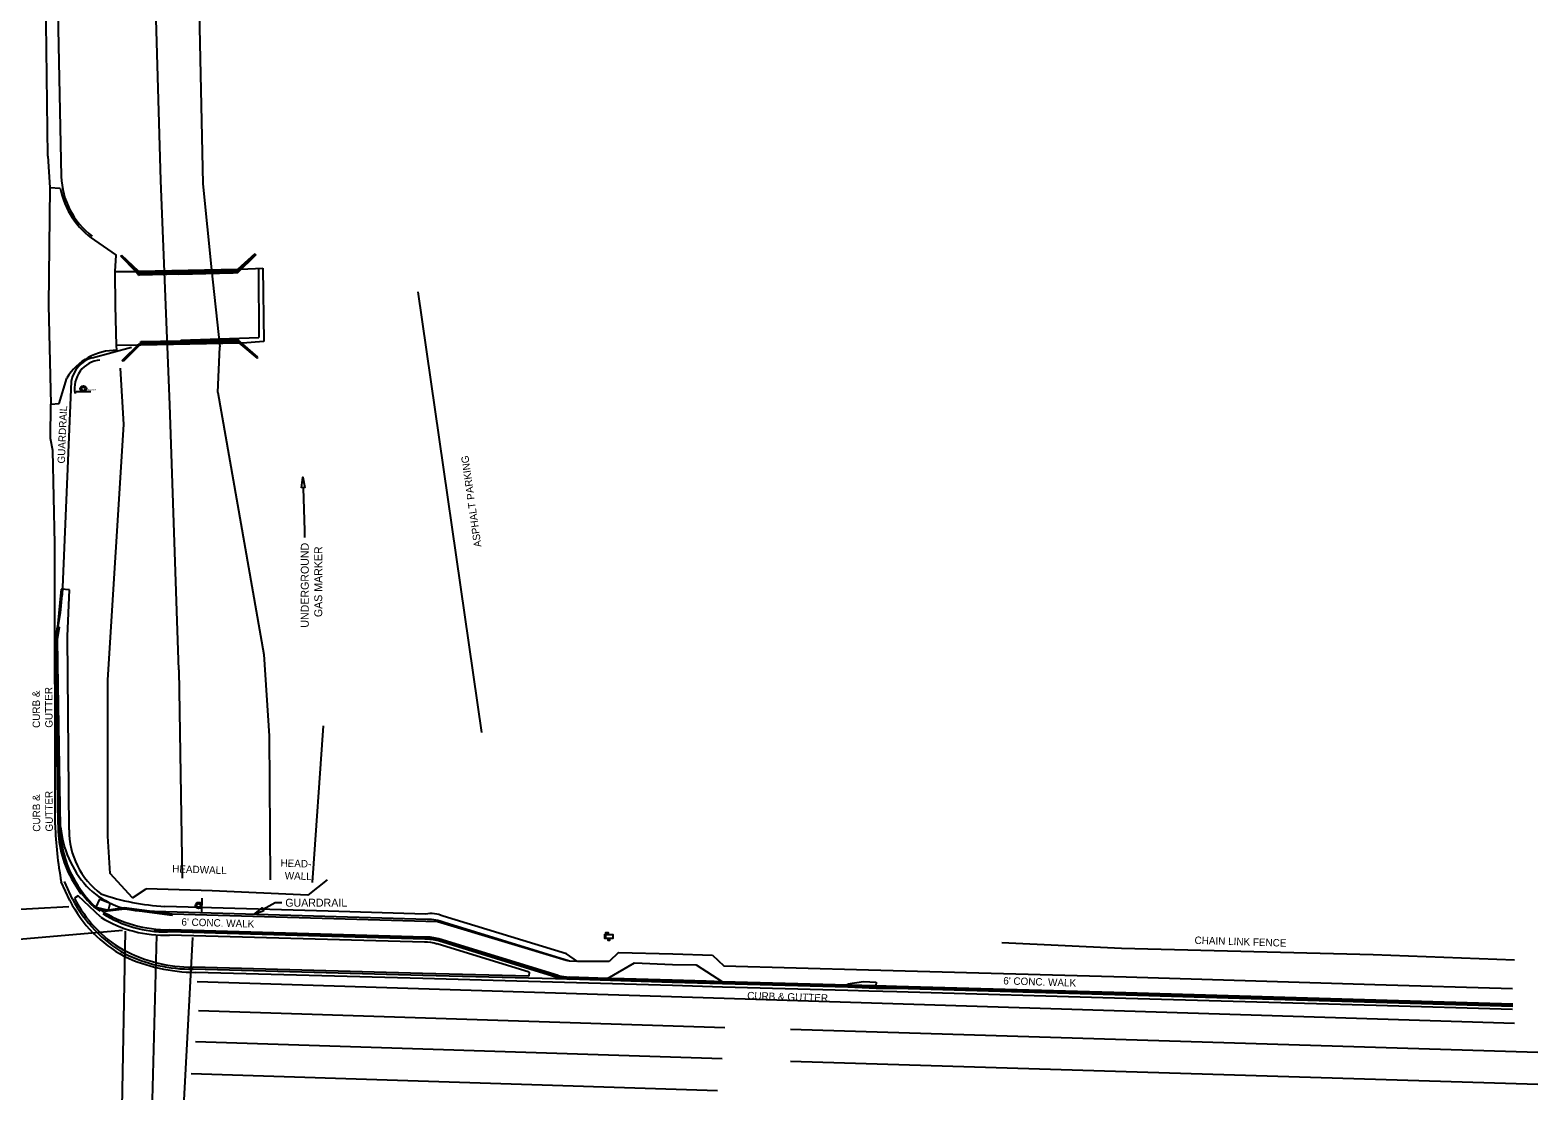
# Model space of a CAD drawing. Extents: x 925226 to 926411, y 852913 to 858733.
# Drawn here: x 925841 to 926411, y 853587 to 853988 of the extents above; entities that cross this region are included whole.
import ezdxf

# ---------------------------------------------------------------- set-up
doc = ezdxf.new("R2010")
doc.units = 0
for name, color, linetype in [('BankMent_ep', 7, 'Continuous'), ('Bridge_ep', 7, 'Continuous'), ('CGep_ep', 7, 'Continuous'), ('CGFace_ep', 7, 'Continuous'), ('CLConst_dp', 7, 'Continuous'), ('ConcSlabs_ep', 7, 'Continuous'), ('CurveData_dp', 7, 'Continuous'), ('EndTreat_ep', 7, 'Continuous'), ('Fence_ep', 7, 'Continuous'), ('Gates_ep', 7, 'Continuous'), ('GuardrailRt_ep', 7, 'Continuous'), ('InletCurb_ep', 7, 'Continuous'), ('LaneLine_ep', 7, 'Continuous'), ('ManholeSW_ep', 7, 'Continuous'), ('PavtAsphalt_ep', 7, 'Continuous'), ('PavtMisc_ep', 7, 'Continuous'), ('SidewalkBack_ep', 7, 'Continuous'), ('SidewalkFront_ep', 7, 'Continuous'), ('TextLabel', 7, 'Continuous'), ('Wall_ep', 7, 'Continuous'), ('WaterEdge_ep', 7, 'Continuous'), ('XSPt_ep', 7, 'Continuous')]:
    doc.layers.add(name, color=color, linetype=linetype)

# ---------------------------------------------------------------- blocks, each defined once
blk = doc.blocks.new('SSS')
at = {"layer": 'ManholeSW_ep'}
blk.add_line((-2.77, 1.15), (2.77, 1.15), dxfattribs=at)
for radius in [1.15, 0.692]:
    blk.add_circle((0, 0), radius, dxfattribs=at)
blk = doc.blocks.new('MBX')
at = {"layer": 'InletCurb_ep'}
for points in [[(-1.5, 1.42), (-1.5, 1.45), (1.5, 1.45), (1.5, 0), (-1.5, 0), (-1.5, 1.42), (-1.53, 1.55), (-1.59, 1.55)], [(-1.15, 0.38), (-1.15, 2.22), (-0.33, 2.22), (-0.33, 1.7), (-1.15, 1.7)], [(0.26, 0), (0.26, -0.82), (-0.26, -0.82), (-0.26, 0)]]:
    blk.add_lwpolyline(points, dxfattribs=at)

msp = doc.modelspace()

# ---------------------------------------------------------------- linework, layer by layer
at = {"layer": 'BankMent_ep'}
for p, q in [((925876.44, 853839.31), (925875.18, 853860.58)), ((925870.39, 853742.68), (925876.44, 853839.31)), ((925870.45, 853683.6), (925870.39, 853742.68)), ((925951.92, 853725.35), (925947.74, 853665.99)), ((925871.27, 853669.48), (925870.45, 853683.6)), ((925879.75, 853660.25), (925871.27, 853669.48)), ((925879.75, 853660.25), (925884.96, 853663.59)), ((925909.87, 853662.89), (925884.96, 853663.59)), ((925953.4, 853667.04), (925946.05, 853661.26)), ((925946.05, 853661.26), (925909.87, 853662.89))]:
    msp.add_line(p, q, dxfattribs=at)
at = {"layer": 'Bridge_ep'}
for p, q in [((925873.15, 853897.17), (925881.02, 853897.13)), ((925882.05, 853897.32), (925919.48, 853897.96)), ((925920.64, 853898.07), (925929.06, 853898.46)), ((925929.06, 853898.46), (925929.41, 853870.63)), ((925881.54, 853869.34), (925873.74, 853869.22)), ((925882.92, 853869.31), (925881.54, 853869.34)), ((925920.14, 853870.02), (925882.92, 853869.31)), ((925921.38, 853870.02), (925920.14, 853870.02)), ((925929.41, 853870.63), (925921.38, 853870.02))]:
    msp.add_line(p, q, dxfattribs=at)
at = {"layer": 'CGep_ep'}
for p, q in [((925850.65, 853757.74), (925851.41, 853762.71)), ((925851.66, 853687.93), (925850.65, 853757.74)), ((925857.09, 853659.68), (925854.03, 853666.46)), ((925856.64, 853667.45), (925860.24, 853661.73)), ((925859.23, 853660.94), (925857.8, 853660.08)), ((925893.59, 853647.4), (925892.98, 853647.33)), ((925990.34, 853644.59), (925893.59, 853647.4)), ((926029.95, 853633.3), (925995.47, 853643.92)), ((925989.54, 853630.9), (925902.76, 853633.29)), ((926029.47, 853629.81), (925989.54, 853630.9)), ((926044.86, 853629.41), (926029.47, 853629.81)), ((926040.18, 853630.11), (926029.95, 853633.3)), ((926040.18, 853630.11), (926044.86, 853629.41)), ((926083.86, 853628.22), (926044.86, 853629.41)), ((926102.88, 853627.7), (926083.86, 853628.22)), ((926150.29, 853626.37), (926102.88, 853627.7)), ((926161.01, 853625.99), (926150.29, 853626.37)), ((926168.8, 853625.88), (926161.01, 853625.99)), ((926255.46, 853623.45), (926168.8, 853625.88)), ((926349.95, 853620.65), (926255.46, 853623.45)), ((926401.72, 853619.15), (926349.95, 853620.65))]:
    msp.add_line(p, q, dxfattribs=at)
for centre, major_axis, ratio, start_param, end_param in [((925893.23, 853687.22), (-20.36, -36.27), 0.999395, 5.206547, 5.718928), ((925902.75, 853683.67), (25.91, 44.61), 0.999831, 2.580594, 3.138774), ((925892.15, 853690.67), (43.15, -5.25), 0.996981, 4.258424, 4.852123), ((925990.45, 853625.44), (-18.17, 6.16), 0.997806, 4.773991, 5.044504), ((925901.75, 853689.84), (54.38, -16.37), 0.995709, 4.546866, 5.021347)]:
    msp.add_ellipse(centre, major_axis=major_axis, ratio=ratio, start_param=start_param, end_param=end_param, dxfattribs=at)
at = {"layer": 'CGFace_ep'}
for p, q in [((925850.9, 853757.86), (925851.75, 853762.45)), ((925851.93, 853687.92), (925850.9, 853757.86)), ((925867.6, 853655.16), (925865.1, 853656.77)), ((925876.78, 853655.94), (925869.32, 853655.01)), ((925894.76, 853653.59), (925876.78, 853655.94)), ((925894.76, 853653.59), (925894.7, 853654.09)), ((925990.5, 853644.88), (925893.82, 853647.75)), ((926039.03, 853630.79), (925995.48, 853644.25)), ((926042, 853630.1), (926039.03, 853630.79)), ((926044.87, 853629.81), (926042, 853630.1)), ((926059.38, 853629.37), (926044.87, 853629.81)), ((926065.64, 853629.11), (926059.38, 853629.37)), ((926096.52, 853628.23), (926065.64, 853629.11)), ((926102.86, 853628.11), (926096.52, 853628.23)), ((926150.25, 853626.64), (926102.86, 853628.11)), ((926158.37, 853626.47), (926150.25, 853626.64)), ((926160.95, 853626.43), (926158.37, 853626.47)), ((926168.82, 853626.28), (926160.95, 853626.43)), ((926255.43, 853623.81), (926168.82, 853626.28)), ((926349.93, 853621.05), (926255.43, 853623.81)), ((926401.75, 853619.54), (926349.93, 853621.05))]:
    msp.add_line(p, q, dxfattribs=at)
for centre, major_axis, ratio, start_param, end_param in [((925894.52, 853687.62), (-12.79, -40.67), 0.998791, 5.00943, 5.506476), ((925898.69, 853690.72), (-41.6, -23.45), 0.999835, 6.276271, 6.560771), ((925891.5, 853690.14), (-41.34, 13.97), 0.968786, 1.801218, 1.940513), ((925991.52, 853632.85), (-9.53, 7.41), 0.99977, 5.038512, 5.457491)]:
    msp.add_ellipse(centre, major_axis=major_axis, ratio=ratio, start_param=start_param, end_param=end_param, dxfattribs=at)
at = {"layer": 'ConcSlabs_ep'}
for p, q in [((925867.31, 853659.78), (925865.88, 853656.64)), ((925871.37, 853658.14), (925867.31, 853659.78)), ((925870.66, 853655.6), (925871.37, 853658.14)), ((925865.88, 853656.64), (925870.66, 853655.6))]:
    msp.add_line(p, q, dxfattribs=at)
at = {"layer": 'CurveData_dp'}
for p, q in [((925851.39, 854002.8), (925852.81, 853933.11)), ((925856.59, 853855.59), (925853.21, 853774.71))]:
    msp.add_line(p, q, dxfattribs=at)
for centre, major_axis, ratio, start_param, end_param in [((925882.07, 853933.97), (-7.43, 28.37), 0.997942, 1.344347, 2.242113), ((925890.55, 853690.56), (8.5, -37.79), 0.985079, 4.58536, 5.227098), ((925884.8, 853686.47), (-28.37, -13.24), 0.999822, 0.333748, 1.103783)]:
    msp.add_ellipse(centre, major_axis=major_axis, ratio=ratio, start_param=start_param, end_param=end_param, dxfattribs=at)
at = {"layer": 'EndTreat_ep'}
for p, q in [((925855.72, 853656.82), (925794.38, 853653.47)), ((925784.3, 853639.95), (925875.93, 853647.95)), ((925874.28, 853500.75), (925877.09, 853647.61)), ((925888.87, 853646.07), (925884.89, 853500.54)), ((925897.87, 853558.21), (925902.53, 853645.16)), ((925904.2, 853628.61), (926402.38, 853612.8)), ((925904.7, 853617.57), (926103.8, 853611.12)), ((925903.62, 853605.91), (926102.72, 853599.46)), ((925901.9, 853593.82), (926101, 853587.37))]:
    msp.add_line(p, q, dxfattribs=at)
at = {"layer": 'Fence_ep'}
for p, q in [((925897.34, 853896.11), (925917.78, 853896.61)), ((925897.99, 853871.17), (925927.56, 853872.19)), ((926253.73, 853641.04), (926208.51, 853643.17)), ((926348.9, 853638.61), (926253.73, 853641.04)), ((926402.33, 853636.64), (926348.9, 853638.61))]:
    msp.add_line(p, q, dxfattribs=at)
at = {"layer": 'Gates_ep'}
msp.add_line((925927.36, 853898.16), (925927.56, 853872.19), dxfattribs=at)
at = {"layer": 'GuardrailRt_ep'}
for p, q in [((925864.51, 853864.54), (925879.36, 853868.56)), ((925852.52, 853768.1), (925853.21, 853774.71)), ((925851.5, 853762), (925852.52, 853768.1)), ((925851.34, 853756.09), (925851.5, 853762)), ((925852.55, 853687.04), (925851.34, 853756.09)), ((925991.17, 853652.08), (925883.85, 853655.18)), ((926045.04, 853636.32), (925997.63, 853650.84))]:
    msp.add_line(p, q, dxfattribs=at)
for centre, major_axis, ratio, start_param, end_param in [((925867.81, 853853.6), (-4.22, -10.63), 0.997065, 3.814485, 4.914703), ((925991.29, 853635.33), (-7.46, 15), 0.999858, 5.433542, 5.828738)]:
    msp.add_ellipse(centre, major_axis=major_axis, ratio=ratio, start_param=start_param, end_param=end_param, dxfattribs=at)
at = {"layer": 'LaneLine_ep'}
for p, q in [((926128.6, 853610.54), (926411.2, 853601.9)), ((926128.6, 853598.44), (926411.2, 853589.8))]:
    msp.add_line(p, q, dxfattribs=at)
at = {"layer": 'PavtAsphalt_ep'}
for p, q in [((925847.73, 853940.75), (925846.94, 854002.63)), ((925847.73, 853940.75), (925848.45, 853928.88)), ((925848.45, 853928.88), (925848.01, 853884.4)), ((925848.45, 853928.88), (925852.45, 853928.7)), ((925865.39, 853909.01), (925873.58, 853903.38)), ((925873.15, 853897.17), (925873.58, 853903.38)), ((925873.28, 853884.15), (925873.15, 853897.17)), ((925848.01, 853884.4), (925848.9, 853847)), ((925873.74, 853869.22), (925873.28, 853884.15)), ((925852.07, 853847.28), (925854.91, 853856.84)), ((925848.78, 853833.95), (925848.9, 853847)), ((925848.9, 853847), (925852.07, 853847.28)), ((925849.64, 853829.49), (925848.78, 853833.95)), ((925850.39, 853794.1), (925849.64, 853829.49)), ((925850.53, 853687.86), (925850.39, 853794.1)), ((925856.12, 853659.17), (925852.84, 853666.23)), ((925867.75, 853652.95), (925859.23, 853660.94)), ((925990.14, 853643.46), (925893.73, 853646.16)), ((926029.79, 853632.06), (925994.98, 853642.77)), ((925989.51, 853629.75), (925903.56, 853632.04)), ((926029.52, 853628.62), (925989.51, 853629.75)), ((926029.79, 853632.06), (926029.6, 853630.55)), ((926083.92, 853627.07), (926029.52, 853628.62)), ((926102.83, 853626.49), (926083.92, 853627.07)), ((926150.22, 853625.15), (926102.83, 853626.49)), ((926158.24, 853624.98), (926150.22, 853625.15)), ((926168.78, 853624.65), (926158.24, 853624.98)), ((926255.37, 853622.19), (926168.78, 853624.65)), ((926350, 853619.47), (926255.37, 853622.19)), ((926401.59, 853618), (926350, 853619.47))]:
    msp.add_line(p, q, dxfattribs=at)
for centre, major_axis, ratio, start_param, end_param in [((925882.74, 853934.55), (-6.37, 30.26), 0.997873, 1.554304, 2.336277), ((925873.75, 853845.27), (-21.18, 6.33), 0.999329, 4.996946, 6.023145), ((925984.01, 853691.49), (13.87, 133.56), 0.994346, 1.700665, 1.862915), ((925900.01, 853681.4), (42.85, 24.17), 0.999822, 3.096732, 3.705466), ((925891.57, 853690.86), (44.75, -2.56), 0.998302, 4.20931, 4.817697), ((925990.12, 853625.95), (-16.94, 4.82), 0.993534, 4.708376, 4.987154), ((925903.93, 853696.69), (61.6, -20.26), 0.996696, 4.595768, 5.023448)]:
    msp.add_ellipse(centre, major_axis=major_axis, ratio=ratio, start_param=start_param, end_param=end_param, dxfattribs=at)
at = {"layer": 'PavtMisc_ep'}
for p, q in [((925987.69, 853889.52), (926011.72, 853722.74)), ((925873.88, 853867.37), (925873.74, 853869.22)), ((925852.83, 853777), (925851.41, 853762.71)), ((925855.87, 853776.78), (925852.83, 853777)), ((925855.18, 853759.15), (925855.87, 853776.78)), ((925855.75, 853685.89), (925855.18, 853759.15)), ((925953.78, 853655.15), (925891.97, 853656.98)), ((925990.55, 853654.1), (925953.78, 853655.15)), ((926043.91, 853638.98), (925997.24, 853653.25)), ((926048.01, 853636.17), (926043.91, 853638.98))]:
    msp.add_line(p, q, dxfattribs=at)
for centre, major_axis, ratio, start_param, end_param in [((925868.47, 853853.05), (-1.34, -10.58), 0.997713, 3.36443, 5.031975), ((925885.76, 853685.77), (-29.32, 6.36), 0.999709, 0.209542, 1.143327), ((925896.76, 853744.45), (87.83, 3.94), 0.996393, 4.332222, 4.613167), ((925992.62, 853643.61), (-6.38, 8.58), 0.999473, 5.196305, 5.838523)]:
    msp.add_ellipse(centre, major_axis=major_axis, ratio=ratio, start_param=start_param, end_param=end_param, dxfattribs=at)
at = {"layer": 'SidewalkBack_ep'}
for p, q in [((925995.13, 853651.1), (925894.7, 853654.09)), ((926043.74, 853636.47), (925995.13, 853651.1)), ((926045.04, 853636.32), (926043.74, 853636.47)), ((926048.01, 853636.17), (926045.04, 853636.32)), ((926060.04, 853636.14), (926048.01, 853636.17)), ((926059.4, 853629.75), (926069.6, 853635.64)), ((926063.55, 853639.57), (926060.04, 853636.14)), ((926063.55, 853639.57), (926084.07, 853639.07)), ((926069.6, 853635.64), (926084.02, 853634.99)), ((926084.02, 853634.99), (926092.95, 853634.87)), ((926084.07, 853639.07), (926099.11, 853638.54)), ((926092.95, 853634.87), (926102.84, 853628.49)), ((926099.11, 853638.54), (926103.35, 853634.48)), ((926103.35, 853634.48), (926158.09, 853632.99)), ((926158.09, 853632.99), (926255.58, 853630.29)), ((926255.58, 853630.29), (926349.58, 853627.45)), ((926349.58, 853627.45), (926401.65, 853625.97))]:
    msp.add_line(p, q, dxfattribs=at)
at = {"layer": 'SidewalkFront_ep'}
for p, q in [((926150.26, 853627.18), (926150.28, 853627.75)), ((926150.28, 853627.75), (926156.23, 853628.54)), ((926156.23, 853628.54), (926160.92, 853628.31)), ((926160.92, 853628.31), (926160.9, 853626.93))]:
    msp.add_line(p, q, dxfattribs=at)
at = {"layer": 'TextLabel'}
for points in [[(925943.62, 853815.34), (925944.15, 853819.36), (925944.95, 853815.39)], [(925929.43, 853655.33), (925925.61, 853653.97), (925928.78, 853656.5)]]:
    msp.add_lwpolyline(points, close=True, dxfattribs=at)
for points in [[(925944.28, 853815.36), (925944.81, 853799.02)], [(925944.81, 853799.02), (925944.81, 853796.49)], [(925929.11, 853655.91), (925933.71, 853658.47)], [(925933.71, 853658.47), (925936.25, 853658.47)]]:
    msp.add_lwpolyline(points, dxfattribs=at)
at = {"layer": 'Wall_ep'}
for p, q in [((925875.32, 853902.93), (925875.69, 853903.23)), ((925881.75, 853896.7), (925875.32, 853902.93)), ((925882.22, 853896.48), (925875.32, 853902.93)), ((925881.02, 853897.13), (925875.32, 853902.93)), ((925875.69, 853903.23), (925882.21, 853897.14)), ((925882.05, 853897.32), (925875.69, 853903.23)), ((925919.41, 853897.9), (925925.98, 853903.84)), ((925919.41, 853897.34), (925926.37, 853903.51)), ((925919.43, 853896.63), (925926.37, 853903.51)), ((925925.98, 853903.84), (925919.48, 853897.96)), ((925926.37, 853903.51), (925919.77, 853897.57)), ((925926.37, 853903.51), (925920.64, 853898.07)), ((925925.98, 853903.84), (925926.37, 853903.51)), ((925882.07, 853895.81), (925881.02, 853897.13)), ((925882.21, 853897.14), (925882.05, 853897.32)), ((925882.16, 853896.68), (925919.34, 853897.35)), ((925882.21, 853897.14), (925882.16, 853896.68)), ((925919.41, 853897.9), (925882.21, 853897.14)), ((925882.22, 853896.48), (925919.41, 853897.34)), ((925919.34, 853897.35), (925919.41, 853897.9)), ((925919.34, 853897.35), (925919.77, 853897.57)), ((925919.34, 853897.35), (925919.41, 853897.34)), ((925920.64, 853898.07), (925919.41, 853896.69)), ((925919.48, 853897.96), (925919.41, 853897.9)), ((925919.41, 853897.34), (925919.43, 853896.63)), ((925882.16, 853896.68), (925881.75, 853896.7)), ((925919.41, 853896.69), (925882.07, 853895.81)), ((925882.07, 853895.81), (925882.24, 853895.95)), ((925882.16, 853896.68), (925882.22, 853896.48)), ((925882.22, 853896.48), (925882.24, 853895.95)), ((925919.43, 853896.63), (925882.24, 853895.95)), ((925919.43, 853896.63), (925919.41, 853896.69)), ((925875.88, 853863.47), (925882.37, 853869.9)), ((925882.63, 853869.51), (925876.25, 853863.13)), ((925882.37, 853869.9), (925882.93, 853869.92)), ((925882.63, 853869.51), (925882.37, 853869.9)), ((925919.93, 853870.19), (925882.63, 853869.51)), ((925920, 853870.88), (925882.93, 853870.18)), ((925882.93, 853870.18), (925882.95, 853870.69)), ((925882.93, 853869.92), (925919.89, 853870.57)), ((925882.93, 853869.92), (925882.93, 853870.18)), ((925882.95, 853870.69), (925919.98, 853871.3)), ((925919.89, 853870.57), (925920, 853870.88)), ((925920.51, 853870.61), (925919.89, 853870.57)), ((925919.89, 853870.57), (925919.93, 853870.19)), ((925919.93, 853870.19), (925926.87, 853864.33)), ((925920, 853870.88), (925919.98, 853871.3)), ((925927.21, 853864.73), (925920.51, 853870.61)), ((925876.25, 853863.13), (925875.88, 853863.47)), ((925926.87, 853864.33), (925927.21, 853864.73))]:
    msp.add_line(p, q, dxfattribs=at)
at = {"layer": 'WaterEdge_ep'}
for p, q in [((925890.48, 853931.53), (925887.87, 854018.96)), ((925904.38, 854019.34), (925906.39, 853930.37)), ((925893.85, 853846.69), (925890.48, 853931.53)), ((925906.39, 853930.37), (925909.59, 853897.75)), ((925925.98, 853903.84), (925926.37, 853903.51)), ((925909.59, 853897.75), (925912.82, 853868.67)), ((925912.01, 853851.41), (925912.82, 853868.67)), ((925912.01, 853851.41), (925929.48, 853752.31)), ((925897.26, 853746.49), (925893.85, 853846.69)), ((925929.48, 853752.31), (925931.5, 853721.46)), ((925897.26, 853746.49), (925898.58, 853667.66)), ((925931.5, 853721.46), (925931.82, 853667.01))]:
    msp.add_line(p, q, dxfattribs=at)
at = {"layer": 'XSPt_ep'}
for p, q in [((925851.34, 853757.99), (925852.1, 853762.61)), ((925851.75, 853762.45), (925851.41, 853762.71)), ((925852.1, 853762.61), (925851.75, 853762.45)), ((925852.35, 853688.17), (925851.34, 853757.99)), ((925865.88, 853656.64), (925865.74, 853656.77)), ((925867.61, 853655.63), (925865.88, 853656.64)), ((925869.17, 853655.49), (925867.61, 853655.63)), ((925870.66, 853655.6), (925869.17, 853655.49)), ((925876.55, 853656.46), (925870.66, 853655.6)), ((925894.7, 853654.09), (925876.55, 853656.46)), ((925990.3, 853645.38), (925893.78, 853648.18)), ((926040.77, 853630.82), (925995.63, 853644.69)), ((925989.48, 853631.64), (925902.7, 853634.02)), ((926029.6, 853630.55), (925989.48, 853631.64)), ((926059.4, 853629.75), (926044.95, 853630.24)), ((926065.66, 853629.61), (926059.4, 853629.75)), ((926083.8, 853629.08), (926065.66, 853629.61)), ((926096.71, 853628.7), (926083.8, 853629.08)), ((926102.84, 853628.49), (926096.71, 853628.7)), ((926150.26, 853627.18), (926102.84, 853628.49)), ((926160.9, 853626.93), (926150.26, 853627.18)), ((926168.62, 853626.68), (926160.9, 853626.93)), ((926255.38, 853624.25), (926168.62, 853626.68)), ((926349.95, 853621.5), (926255.38, 853624.25)), ((926401.79, 853619.99), (926349.95, 853621.5))]:
    msp.add_line(p, q, dxfattribs=at)
for centre, major_axis, ratio, start_param, end_param in [((925894.31, 853687.68), (-9.04, -41.04), 0.998476, 4.917307, 5.419819), ((925896.47, 853688.91), (-41.84, 15.12), 0.999485, 0.840017, 1.155034), ((925900.3, 853681.75), (-10.74, -46.49), 0.999741, 5.410965, 5.976705), ((925892.02, 853692.26), (-43.17, 14.58), 0.963749, 1.31779, 1.924374), ((925902.29, 853689.21), (53.02, -15.88), 0.996946, 4.508077, 5.00992), ((925990.51, 853625.74), (-19.43, 4.15), 0.988213, 4.659696, 4.930755), ((926045.82, 853652.23), (21.32, -5.59), 0.998146, 4.737472, 4.929235)]:
    msp.add_ellipse(centre, major_axis=major_axis, ratio=ratio, start_param=start_param, end_param=end_param, dxfattribs=at)

# ---------------------------------------------------------------- block references
at = {"layer": 'InletCurb_ep'}
msp.add_blockref('MBX', (926059.91, 853644.88), dxfattribs=at)
at = {"layer": 'ManholeSW_ep'}
for p, rotation in [((925861.17, 853852.75), 180), ((925904.74, 853657.36), -91.29444214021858)]:
    msp.add_blockref('SSS', p, dxfattribs=dict(at, rotation=rotation))

# ---------------------------------------------------------------- texts
at = {"layer": 'CLConst_dp'}
msp.add_text('SPEED LIMIT', height=0.5, dxfattribs=at).set_placement((925862.11, 853852.24))
at = {"layer": 'TextLabel'}
for s, height, rotation, p in [('GUARDRAIL', 2.8, 87.6077, (925854.16, 853824.48)), ('ASPHALT PARKING ', 2.8, 98.1996, (926011.74, 853793.1)), ('UNDERGROUND', 3, 90, (925946.41, 853762.43)), ('GAS MARKER', 3, 90, (925951.5, 853766.43)), ('CURB & ', 2.8, 90.5061, (925844.8, 853724.51)), ('GUTTER', 2.8, 90.5061, (925849.56, 853724.59)), ('CURB & ', 2.8, 90.5061, (925844.9, 853685.25)), ('GUTTER', 2.8, 90.5061, (925849.66, 853685.32)), ('HEAD-', 2.8, 358.1724, (925935.69, 853672.02)), ('HEADWALL', 2.8, 358.1724, (925894.73, 853669.85)), ('WALL', 2.8, 358.1724, (925937.3, 853667.26)), ('GUARDRAIL', 3, 360, (925937.54, 853656.88)), ("6' CONC. WALK", 2.8, 358.3396, (925898.22, 853649.75)), ('CHAIN LINK FENCE', 2.8, 358.1724, (926281.35, 853642.83)), ("6' CONC. WALK", 2.8, 358.1724, (926209.01, 853627.49)), ('CURB & GUTTER', 2.8, 358.1724, (926112.19, 853621.89))]:
    msp.add_text(s, height=height, rotation=rotation, dxfattribs=at).set_placement(p)

doc.saveas('drawing.dxf')
